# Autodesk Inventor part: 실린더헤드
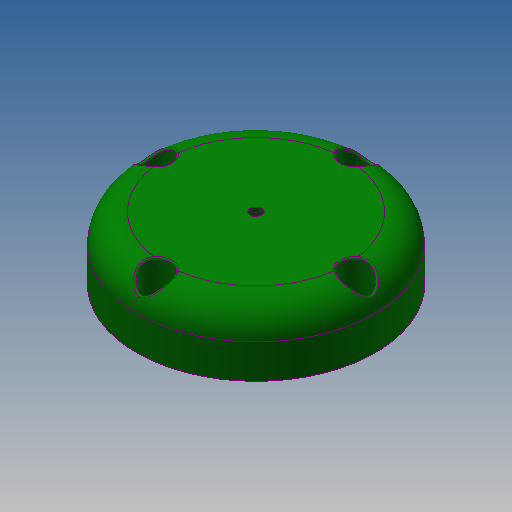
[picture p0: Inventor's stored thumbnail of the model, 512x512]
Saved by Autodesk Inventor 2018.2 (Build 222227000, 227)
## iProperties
Created: 2016-11
Part Number: 실린더헤드
Material: 알루미늄 6061
Document SubType Name: Modeling
Designer: mduedu
Density: 2.71 g/cm^3
Mass: 235.606 g
Surface Area: 209.258 cm^2
Volume: 86.9396 cm^3
Appearance: 진녹색
Author: mduedu
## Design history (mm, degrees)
sketch "스케치1"
  geometry: C1 r 42 at (0, 0); 1 further point
  constraints: 1 centre point, 1 coincident
  dimensions: "d0" = 84 diameter of C1
extrude "돌출1" new body sketch "스케치1" distance "d1" = 22; taper "d2" = 0 deg
fillet "모깎기1" dims "d3" = 10
sketch "스케치2"
  geometry: C1 r 30 at (0, 0); 1 further point
  constraints: 1 centre point, 1 coincident
  dimensions: "d4" = 60 diameter of C1
extrude "돌출2" join sketch "스케치2" distance "d5" = 5; taper "d6" = 0 deg
sketch "스케치3"
  geometry: C1 r 25 at (0, 0); 1 further point
  constraints: 1 centre point, 1 coincident
  dimensions: "d7" = 50 diameter of C1
extrude "돌출3" cut sketch "스케치3" distance "d8" = 18; taper "d9" = 0 deg
hole "구멍1" diameter "d12" = 4.134; stored, may be unused: countersink angle "d16" = 90 deg, drill point angle "d18" = 118 deg; dims "d10" = 10, "d11" = 10, "d13" = 6, "d14" = 4, "d15" = 2, "d17" = 8
chamfer "모따기1" distance "d19" = 1; stored, may be unused: second distance "d20" = 2, angle "d21" = 45 deg
fillet "모깎기2" dims "d22" = 3
sketch "스케치4"
  geometry: C1 r 17.5 at (0, 0); 1 further point
  constraints: 1 centre point, 1 coincident
  dimensions: "d23" = 35 diameter of C1
extrude "돌출4" cut sketch "스케치4" distance "d24" = 3; taper "d25" = 0 deg
fillet "모깎기3" dims "d26" = 0.5
sketch "스케치5" dims "d32" = 70
  geometry: C1 r 5 at (0, 35); 3 further points
  constraints: 2 coincident, 2 vertical alignment, 1 centre point, 2 other
  dimensions: "d33" = 10 diameter of C1
extrude "돌출5" cut sketch "스케치5" distance "d34" = 12; taper "d35" = 0 deg
sketch "스케치6" dims "d39" = 70
  geometry: 6 further points
  constraints: 2 vertical alignment, 1 coincident, 7 other
  dimensions: "d42" = 360 deg dimension on point (0, -35) point (0, 0) (derived)
sketch "스케치7"
  geometry: 4 further points
  constraints: 4 other
hole "구멍2" sketch "스케치7" at (0, 70), (-35, 35), (35, 35), (0, 0) diameter "d44" = 5.5; stored, may be unused: countersink angle "d48" = 90 deg, drill point angle "d50" = 0 deg; dims "d45" = 6, "d46" = 4, "d47" = 2, "d49" = 8
fillet "모깎기4" dims "d51" = 0.5
chamfer "모따기2" distance "d54" = 5; stored, may be unused: second distance "d55" = 2, angle "d56" = 30 deg
node "솔리드1"
pattern_circular "원형 패턴1" dims angle "d37" = 360 deg
